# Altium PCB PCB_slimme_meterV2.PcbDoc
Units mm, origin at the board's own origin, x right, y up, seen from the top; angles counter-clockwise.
Board outline 25.4 x 59.2 mm, 2 copper layers (Top Layer, Bottom Layer); 37 components, 30 nets, 143 pads, 37 vias.
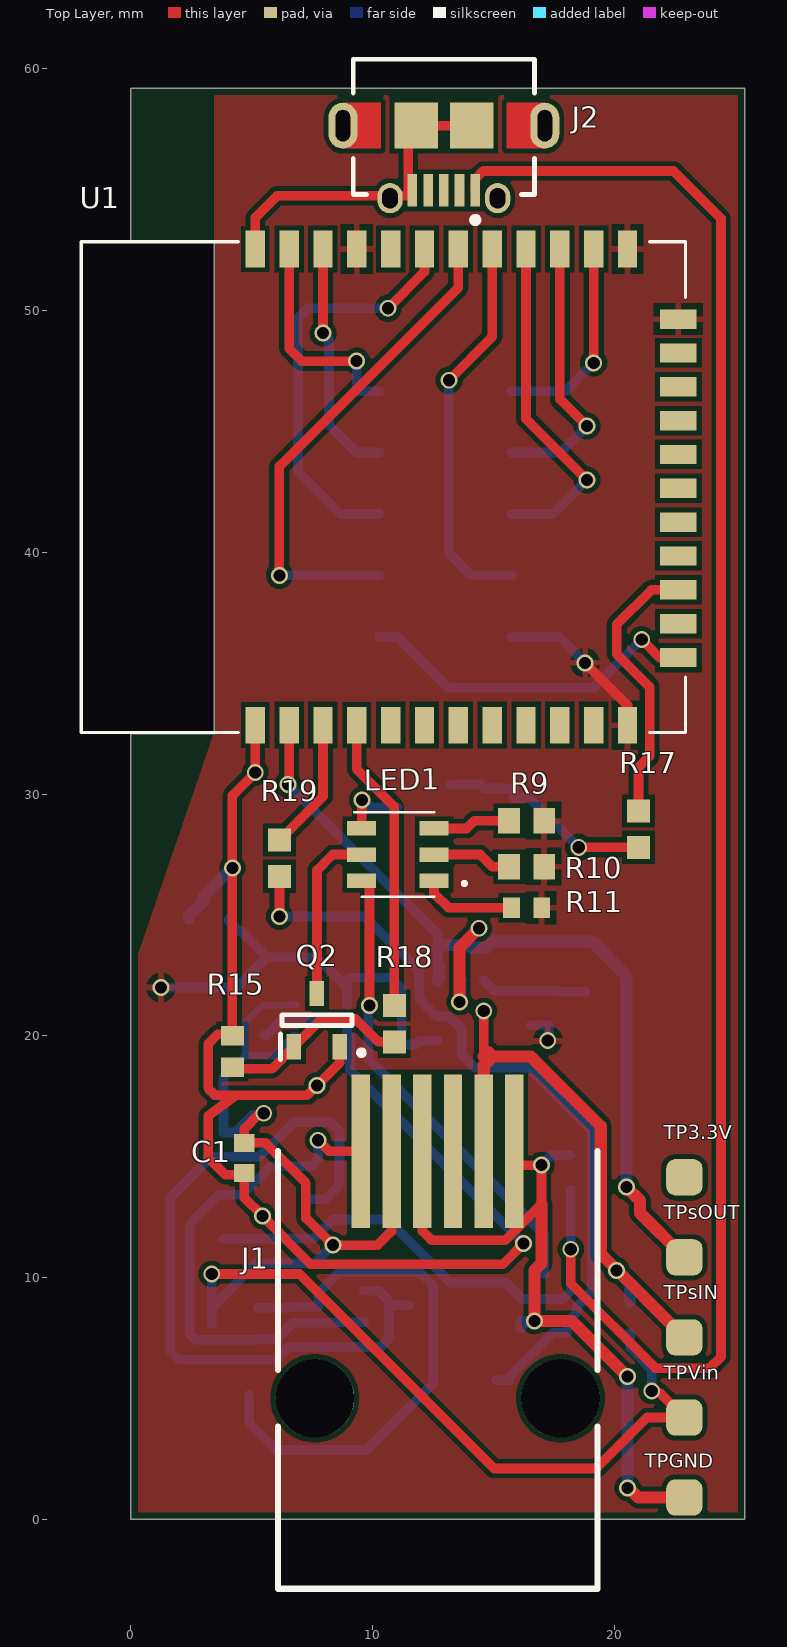
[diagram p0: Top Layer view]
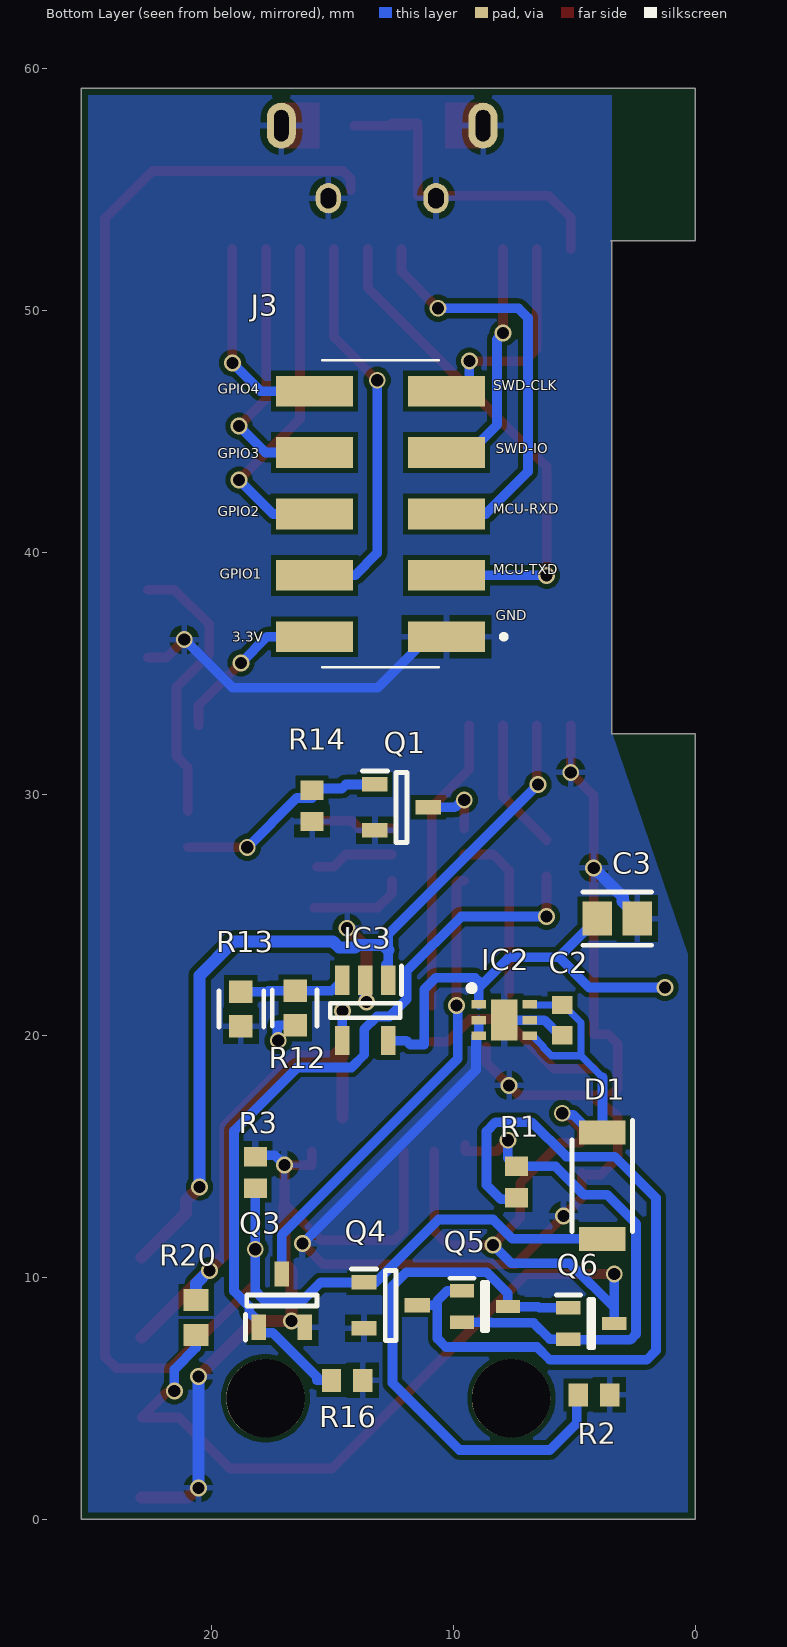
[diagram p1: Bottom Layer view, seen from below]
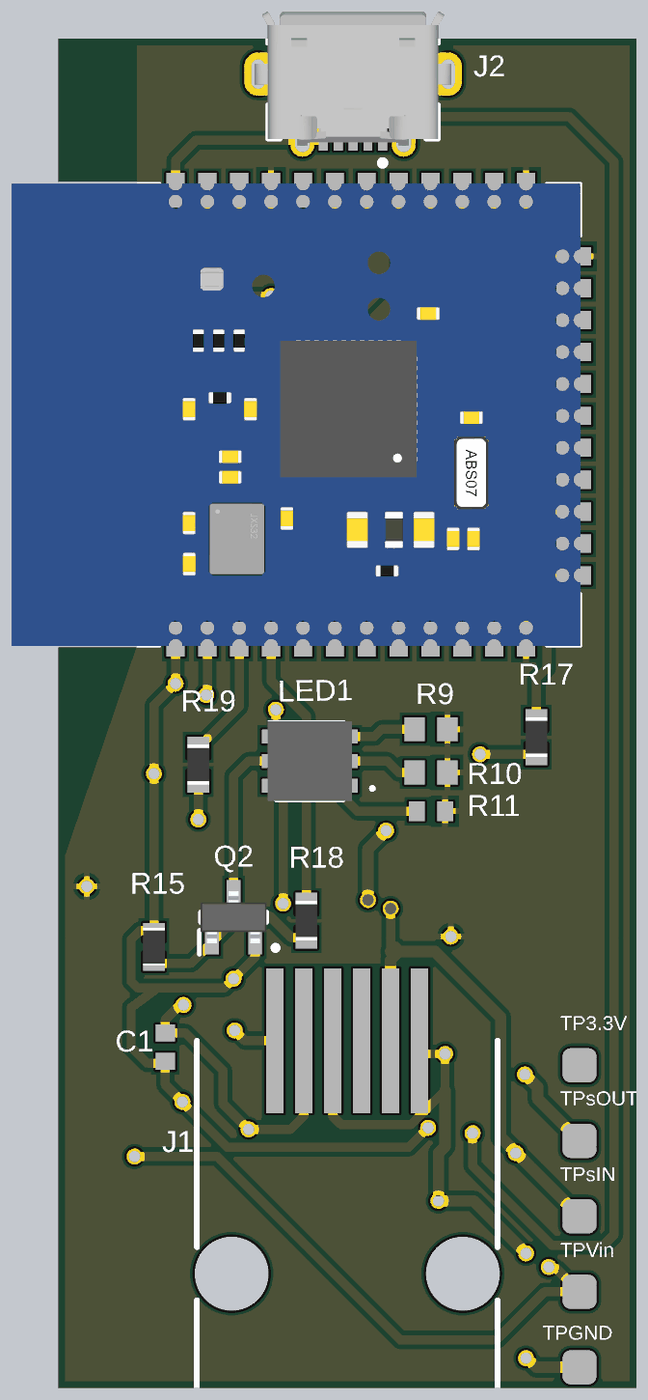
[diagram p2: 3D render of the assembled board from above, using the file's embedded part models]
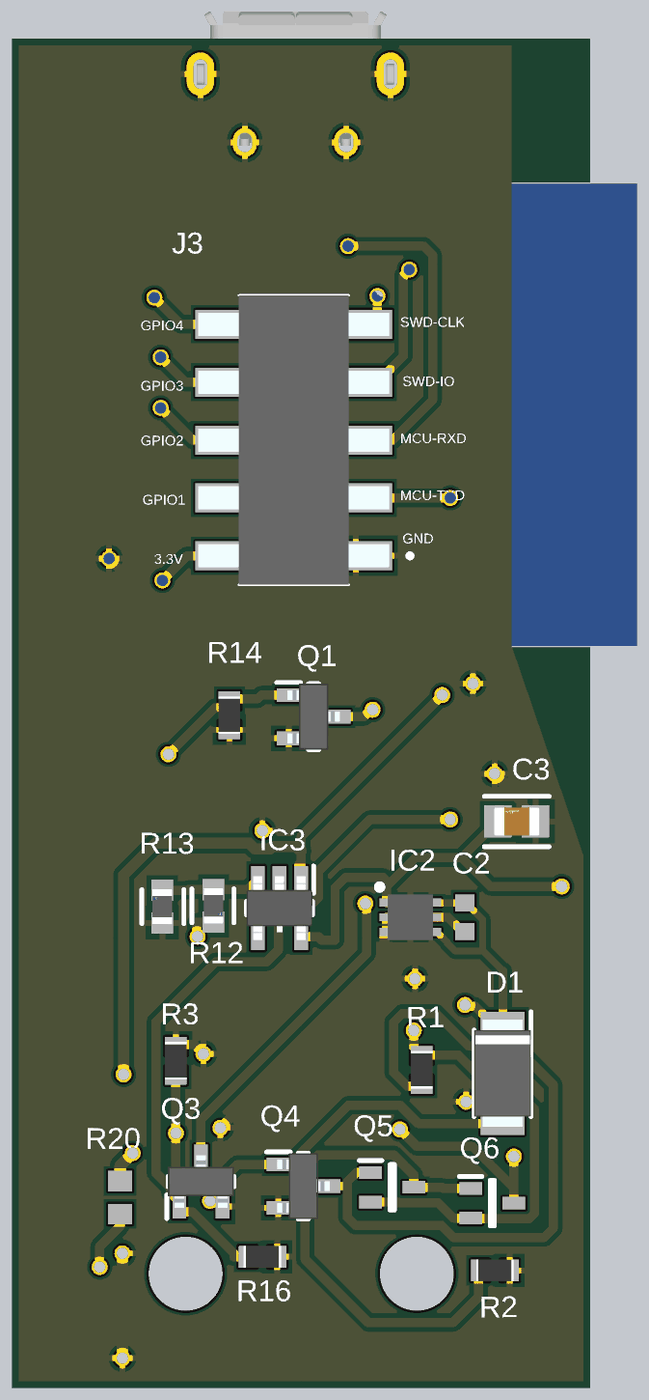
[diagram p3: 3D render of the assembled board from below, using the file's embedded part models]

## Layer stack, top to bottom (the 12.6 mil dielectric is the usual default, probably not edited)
Top Solder: solder mask 0.0102, Solder Resist, Dk 3.5
Top Layer: signal copper 0.0356
Dielectric 1: dielectric 0.32, FR-4, Dk 4.8
Bottom Layer: signal copper 0.0356
Bottom Solder: solder mask 0.0102, Solder Resist, Dk 3.5

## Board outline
3.5,52.9 3.45,52.85 3.45,32.5 0,32.5 0,0 25.4,0 25.4,59.2 0,59.2 0,52.9

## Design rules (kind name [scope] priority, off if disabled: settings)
AssemblyTestpoint [All] p1: testpointundercomponent=TRUE minsize=1 maxsize=2.5 preferedsize=1 minholesize=0 maxholesize=1 preferedholesize=0.8 testpointgrid=0.025 usegrid=TRUE gridtolerance=0 allowsidetop=TRUE allowsidebottom=TRUE
AssemblyTestpoint AssemblyTestpoint_1 [All] p2: testpointundercomponent=TRUE minsize=1.016 maxsize=2.54 preferedsize=1.524 minholesize=0 maxholesize=1.016 preferedholesize=0.813 testpointgrid=0.025 usegrid=TRUE gridtolerance=0 allowsidetop=TRUE allowsidebottom=TRUE
Clearance [All] p1: gap=0.2 ignorepadtopadclearanceinfootprint=FALSE except(0: Arc-Hole Track-Hole SMDPad-Hole THPad-Hole Via-Hole Fill-Hole Poly-Hole Region-Hole Text-Hole)
Clearance Clearance_2 [All] p2: gap=0.254 ignorepadtopadclearanceinfootprint=FALSE except(0: Arc-Hole Track-Hole SMDPad-Hole THPad-Hole Via-Hole Fill-Hole Poly-Hole Region-Hole Text-Hole)
HoleSize HoleSize_1 [All] p1: absolutevalues=TRUE maxlimit=10 minlimit=0.3 maxpercent=80.000 minpercent=20.000
HoleSize [All] p2: absolutevalues=TRUE maxlimit=2.54 minlimit=0.3 maxpercent=80.000 minpercent=20.000
MinimumSolderMaskSliver MinimumSolderMaskSliver_1 [(InComponent('J2') AND InComponent('IC2') AND InComponent('IC3'))] p1: minsoldermaskwidth=0.04
MinimumSolderMaskSliver MinimumSolderMaskSliver_2 [All] p2: minsoldermaskwidth=0.04
MinimumSolderMaskSliver [All] p3: minsoldermaskwidth=0.09
PolygonConnect [All] p1: connectstyle=Relief reliefconductorwidth=0.254 reliefentries=4 polygonreliefangle="90 Angle" airgapwidth=0.254
RoutingVias [All] p1: holewidth=0.5 width=0.7 viastyle="Through Hole" minholewidth=0.3 minwidth=0.4 maxholewidth=1 maxwidth=1.2
RoutingVias RoutingVias_1 [All] p2: holewidth=0.711 width=1.27 viastyle="Through Hole" minholewidth=0.711 minwidth=1.27 maxholewidth=0.711 maxwidth=1.27
SilkToSolderMaskClearance [HasFootprint('SON65P200X200X80-7N') AND (HasFootprint('SODFL4725X110N') AND HasFootprint('SOT65P210X110-3N') AND HasFootprint('SOT95P230X110-3N') AND HasFootprint('MOLX-47589-0001_V'))] p1: minsilkscreentomaskgap=0 clearancetoexposedcopper=TRUE
SilkToSolderMaskClearance SilkToSolderMaskClearance_1 [(InComponent('IC2') AND InComponent('IC3') AND InComponent('LED1') AND InComponent('J1') AND InComponent('J2'))] p2: minsilkscreentomaskgap=0.254 clearancetoexposedcopper=TRUE
SilkToSolderMaskClearance SilkToSolderMaskClearance_2 [IsPad] p3: minsilkscreentomaskgap=0.04 clearancetoexposedcopper=TRUE
SolderMaskExpansion [All] p1: expansion=0.102 istentingtop=FALSE
Width [All] p1: maxlimit=0.7 minlimit=0.3 preferedwidth=0.4
Width Width_1 [All] p2: maxlimit=0.254 minlimit=0.254 preferedwidth=0.254
26 further rules are at their usual default settings.

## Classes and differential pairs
component class Spanningsbronschakelaar: C1 D1 Q4 Q5 Q6 R1 R2 R3
component class schema_slimme_meterV4: C2 C3 IC2 IC3 J1 J2 J3 LED1 Q1 Q2 Q3 R9 R10 R11 R12 R13 R14 R15 R16 R17 R18 R19 R20 TP3.3V TPGND TPsIN TPsOUT TPVin U1

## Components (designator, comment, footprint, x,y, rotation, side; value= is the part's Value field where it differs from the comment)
C1 "1uF, 25V, 0603" CAPC1608X90X35LL10T15 4.7,14.95 r90 top
C2 "1uF, 25V, 0603" CAPC1608X90X35LL10T15 5.5,20.65 r90 bottom
C3 "4.7uF, 35V, 0805" FP-GRM219-0_15-0_1-IPC_B 3.226,24.85 r0 bottom
D1 "PMEG3020EP,115" SODFL4725X110N 3.85,13.8 r270 bottom
IC2 "TPS7A2533DRVR" SON65P200X200X80-7N 7.9,20.65 r180 bottom
IC3 "TLV9101IDBVR" SOT95P280X145-5N 13.65,21.05 r270 bottom
J1 "95501-6669" 95501-6669 12.695,5.007 r0 top
J2 "47589-0001" MOLX-47589-0001_V 12.95,56.15 r180 top
J3 "2x5_2.54mm_smd" 10129383910001ALF 13.02,41.59 r90 bottom
LED1 "L1MC-RGB0035000MP0" L1MCRGB0035000MP0 11.05,27.5 r180 top
Q1 "NX3020NAK,215" SOT95P230X110-3N 12.15,29.45 r180 bottom
Q2 "NX3020NAK,215" SOT95P230X110-3N 7.7,20.65 r90 top
Q3 "NX3020NAK,215" SOT95P230X110-3N 17.1,9.05 r90 bottom
Q4 "NX3020NAK,215" SOT95P230X110-3N 12.6,8.85 r180 bottom
Q5 "NX3008PBKW,115" SOT65P210X110-3N 8.7,8.8 r180 bottom
Q6 "NX3008PBKW,115" SOT65P210X110-3N 4.3,8.1 r180 bottom
R1 "10KΩ, 1/10W, 0603" RESC1609X50X30NL8T20 7.4,13.95 r90 bottom
R2 "10KΩ, 1/10W, 0603" RESC1609X50X30NL8T20 4.185,5.15 r0 bottom
R3 "10KΩ, 1/10W, 0603" RESC1609X50X30NL8T20 18.2,14.35 r270 bottom
R9 "18Ω, 0.1W, 0603" RESC1608X55X30ML15T15 16.375,28.9 r0 top
R10 "33Ω, 0.1W, 0603" RESC1608X55X30ML15T15 16.375,27 r0 top
R11 "82Ω, 0.1W, 0603" RESC1608X55X30LL15T15 16.375,25.3 r0 top
R12 "1MΩ, 1/10W, 0603" FP-CRCW0603-e3-IPC_B 16.55,21.15 r270 bottom
R13 "1MΩ, 1/10W, 0603" FP-CRCW0603-e3-IPC_B 18.8,21.115 r90 bottom
R14 "10KΩ, 1/10W, 0603" RESC1609X50X30NL8T20 15.85,29.515 r90 bottom
R15 "10KΩ, 1/10W, 0603" RESC1609X50X30NL8T20 4.2,19.35 r270 top
R16 "10KΩ, 1/10W, 0603" RESC1609X50X30NL8T20 14.4,5.75 r0 bottom
R17 "4.7KΩ, 1/10W, 0603" RESC1608X55X30NL15T15 21,28.55 r270 top
R18 "4.7KΩ, 1/10W, 0603" RESC1608X55X30NL15T15 10.9,20.5 r270 top
R19 "4.7KΩ, 1/10W, 0603" RESC1608X55X30NL15T15 6.15,27.35 r270 top
R20 "1.5KΩ, 1/10W, 0603" RESC1608X55X30ML15T15 20.65,8.35 r270 bottom
TP3.3V "TP_1" PCBComponent_1 22.9,14.15 r90 top
TPGND "TP_1" PCBComponent_1 22.9,0.9 r90 top
TPsIN "TP_1" PCBComponent_1 22.9,7.525 r90 top
TPsOUT "TP_1" PCBComponent_1 22.9,10.837 r90 top
TPVin "TP_1" PCBComponent_1 22.9,4.213 r90 top
U1 "ACN52832" ACN52832 22.95,32.55 r90 top

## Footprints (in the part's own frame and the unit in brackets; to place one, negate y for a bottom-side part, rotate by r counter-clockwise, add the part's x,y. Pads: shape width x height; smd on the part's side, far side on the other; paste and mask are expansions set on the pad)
95501-6669 [mm]
  rect 0.76x6.35 smd: 1(-3.175,10.225) 2(-1.905,10.225) 3(-0.635,10.225) 4(0.635,10.225) 5(1.905,10.225) 6(3.175,10.225)
  round 3.25 hole 3.25 unplated: 7(-5.08,0) 8(5.08,0)
  silkscreen extent -6.61,-7.88 6.61,14.39, body extent -6.61,-8 6.61,12.55, height 11.75
10129383910001ALF [mm]
  rect 1.27x3.18 smd: A1(-5.08,-2.73) A2(-2.54,-2.73) A3(0,-2.73) A4(2.54,-2.73) A5(5.08,-2.73) B1(-5.08,2.73) B2(-2.54,2.73) B3(0,2.73) B4(2.54,2.73) B5(5.08,2.73)
  silkscreen extent -6.35,-5.2 6.35,2.42, body extent -6.35,-4.19 6.35,4.19, height 9.95
ACN52832 [mm]
  rect 1.524x0.8 smd: 1(0.3,17.8) 2(0.3,16.4) 3(0.3,15) 4(0.3,13.6) 5(0.3,12.2) 6(0.3,10.8) 7(0.3,9.4) 8(0.3,8) 9(0.3,6.6) 10(0.3,5.2) 11(0.3,3.8) 12(0.3,2.4) 24(20,2.4) 25(20,3.8) 26(20,5.2) 27(20,6.6) 28(20,8) 29(20,9.4) 30(20,10.8) 31(20,12.2) 32(20,13.6) 33(20,15) 34(20,16.4) 35(20,17.8)
  rect 0.8x1.524 smd: 13(3.1,0.3) 14(4.5,0.3) 15(5.9,0.3) 16(7.3,0.3) 17(8.7,0.3) 18(10.1,0.3) 19(11.5,0.3) 20(12.9,0.3) 21(14.3,0.3) 22(15.7,0.3) 23(17.1,0.3)
  Top Layer pour cut-out: 20.3,25 20.3,19.5 0,19.5 0,25
  Bottom Layer pour cut-out: 20.3,25 20.3,19.5 0,19.5 0,25
  silkscreen extent 0,0 20.3,25, body extent 0,0 20.3,25, height 1.8
CAPC1608X90X35LL10T15 [mm] "Chip Capacitor, 2-Leads, Body 1.60x0.80mm, IPC High Density"
  rect 0.75x0.85 smd: 1(-0.625,0) 2(0.625,0)
  body extent -0.85,-0.45 0.85,0.45, height 0.9
FP-CRCW0603-e3-IPC_B [mm]
  rect 0.935x0.962 smd paste+0 mask+0: 1(-0.715,0) 2(0.715,0)
  silkscreen extent -0.75,-0.95 0.75,0.9, body extent -0.77,-0.43 0.77,0.43, height 0.5
FP-GRM219-0_15-0_1-IPC_B [mm]
  rect 1.206x1.408 smd paste+0 mask+0: 1(-0.826,0) 2(0.826,0)
  silkscreen extent -1.43,-1.1 1.43,1.1, body extent -1,-0.63 1,0.63, height 0.95
L1MCRGB0035000MP0 [mm]
  rect 1.2x0.6 smd: 1(-1.5,1.08) 2(1.5,1.08) 3(-1.5,0) 4(1.5,0) 5(-1.5,-1.08) 6(1.5,-1.08)
  silkscreen extent -2.8,-1.75 1.8,1.75, body extent -1.85,-1.75 1.85,1.75, height 2.9
MOLX-47589-0001_V [mm] "SMD, 5-Leads, Body 7.5x5.6mm, Pitch 0.65mm"
  rect 0.4x1.35 smd: 1(-1.3,1.175) 2(-0.65,1.175) 3(0,1.175) 4(0.65,1.175) 5(1.3,1.175)
  oval 1.05x1.25 hole 0.65 slot 0.85 at 90 deg: 6(-2.225,1.5) 7(2.225,1.5)
  oval 1.2x1.9 hole 0.6 slot 1.3 at 90 deg: 8(-4.175,-1.5) 11(4.175,-1.5)
  rect 1.8x1.9 smd: 9(-1.15,-1.5) 10(1.15,-1.5)
  Top Layer region: 2.6,-2.45 4.175,-2.45 4.175,-0.55 2.6,-0.55
  Top Layer region: -2.6,-0.55 -4.175,-0.55 -4.175,-2.45 -2.6,-2.45
  silkscreen extent -3.75,-4.25 3.75,2.52, body extent -4.32,-4.25 4.32,1.64, height 2.74
PCBComponent_1 [mm]
  rrect50% 1.5x1.5 smd: TP1(0,0)
RESC1608X55X30LL15T15 [mm] "Chip Resistor, 2-Leads, Body 1.60x0.80mm, IPC High Density"
  rect 0.7x0.85 smd: 1(-0.625,0) 2(0.625,0)
  body extent -0.87,-0.48 0.87,0.48, height 0.55
RESC1608X55X30ML15T15 [mm] "Chip Resistor, 2-Leads, Body 1.60x0.80mm, IPC Low Density"
  rect 0.9x1.05 smd: 1(-0.725,0) 2(0.725,0)
  body extent -0.87,-0.48 0.87,0.48, height 0.55
RESC1608X55X30NL15T15 [mm] "Chip Resistor, 2-Leads, Body 1.75x0.95mm, IPC Medium Density"
  rect 0.95x0.95 smd: 1(-0.75,0) 2(0.75,0)
  body extent -0.87,-0.48 0.87,0.48, height 0.55
RESC1609X50X30NL8T20 [mm] "Chip Resistor, 2-Leads, Body 1.65x0.95mm, IPC Medium Density"
  rect 0.8x0.95 smd: 1(-0.65,0) 2(0.65,0)
  body extent -0.82,-0.48 0.82,0.48, height 0.5
SODFL4725X110N [mm]
  rect 1x1.93 smd: 1(-2.2,0) 2(2.2,0)
  silkscreen extent -2.7,-1.25 1.9,1.25, body extent -2.35,-1.25 2.35,1.25, height 1.1
SON65P200X200X80-7N [mm]
  rect 0.6x0.35 smd: 1(-1.05,0.65) 2(-1.05,0) 3(-1.05,-0.65) 4(1.05,-0.65) 5(1.05,0) 6(1.05,0.65)
  rect 1.1x1.7 smd: 7(0,0)
  silkscreen extent -1.48,1.2 -1.23,1.45, body extent -1,-1 1,1, height 0.8
SOT65P210X110-3N [mm]
  rect 1x0.55 smd: 1(-0.95,0.65) 2(-0.95,-0.65) 3(0.95,0)
  silkscreen extent -1.45,-1 0.1,1.17, body extent -1.05,-1.05 1.05,1.05, height 0.95
SOT95P230X110-3N [mm]
  rect 1.05x0.6 smd: 1(-1.1,0.95) 2(-1.1,-0.95) 3(1.1,0)
  silkscreen extent -1.63,-1.45 0.22,1.5, body extent -1.15,-1.45 1.15,1.45, height 1.1
SOT95P280X145-5N [mm]
  rect 1.2x0.6 smd: 1(-1.25,0.95) 2(-1.25,0) 3(-1.25,-0.95) 4(1.25,-0.95) 5(1.25,0.95)
  silkscreen extent -1.85,-1.45 0.3,1.5, body extent -1.4,-1.45 1.4,1.45, height 1.2

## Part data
C1 C2: library part CMP-2006-02459-1, Manufacturer=Murata, Part Number=GRM188R61E105KA12D
C3: library part CMP-06035-049019-1, "Chip Multilayer Ceramic Capacitors for General Purpose, 0805, 4.7uF, X5R, 15%, 10%, 35V", Capacitance=4.7uF, Case Code (Imperial)=0805, Case Code (Metric)=2012, Dielectric=X5R, Dielectric Material=Ceramic, Max Operating Temperature=85°C, Min Operating Temperature=-55°C, Package Quantity=1, Tolerance=10%, Voltage=35V
D1: "Diode", Manufacturer_Name=Nexperia, Mouser2 Part Number=771-PMEG3020EP115
IC2 IC3: "Integrated Circuit", Manufacturer_Name="Texas Instruments"
J1: "Connector", Manufacturer_Name=Molex, Mouser2 Part Number=538-95501-6669
J2: library part CMP-2000-05610-1, "Right Angle Female Type AB Micro USB Connector, 30 V, 1.8 A, -30 to 85 degC, RoHS, Tape and Reel", Color=Black, Current Rating=1.8A, Manufacturer=Molex, Operating Temperature Range=-20Cto+85C, Package Description="Micro USB Connector, Pitch 0.65 mm, 5 Positions, Body 7.5 x 5.6 mm", Voltage Rating=30VAC
J3: "Connector", Manufacturer_Name=Amphenol, Manufacturer_Part_Number=10129383-910001ALF
LED1: "LED", Manufacturer_Name=Lumileds
Q1 Q2 Q3 Q4: "MOSFET (N-Channel)", Manufacturer_Name=Nexperia
Q5 Q6: "MOSFET (P-Channel)", Manufacturer_Name=Nexperia
R1 R2 R3 R14 R15 R16: library part CMP-1666-00005-4, "Chip Resistor, 10 KOhm, +/- 1%, 100 mW, -55 to 155 degC, 0603 (1608 Metric), RoHS, Tape and Reel", Manufacturer="Vishay Semiconductor", Max Operating Temperature="155 degC", Min Operating Temperature="-55 degC", Package Quantity=5000, Voltage Rating="75 V"
R9: library part CMP-2000-00306-1, Manufacturer=Panasonic, Part Number=ERJ3EKF18R0V
R10: library part CMP-2000-00443-1, Manufacturer=Panasonic, Part Number=ERJ3EKF33R0V
R11: library part CMP-2000-00662-1, Manufacturer=Panasonic, Part Number=ERJ3EKF82R0V
R12 R13: library part CMP-2000-03016-2, "RES Thick Film, 1MΩ, 5%, 0.1W, 200ppm/°C, 0603", Case Code (Imperial)=0603, Case Code (Metric)=1608, Max Operating Temperature=155°C, Max Power Dissipation=100mW, Min Operating Temperature=-55°C, Package Quantity=1, Resistance=1MR, Temperature Coefficient=200ppm/°C, Tolerance=5%, Voltage Rating=75V
R17 R18 R19: library part CMP-1012-00586-3, "Precision Thick Film Chip Resistor, 4.7 KOhm, +/- 1%, -55 to 155 degC, 0603 (1608 Metric), RoHS, Tape and Reel", Case Code (Imperial)=1206, Case Code (Metric)=3216, Case\Package=1205, Max Operating Temperature="125 degC", Min Operating Temperature="-55 degC", Package Quantity=1, Power Rating="250 mW", Resistance="220 Ohm", Tolerance=5%, Type (Resistor)="Thick Film", Voltage Rating="50 V"
R20: library part CMP-1012-00528-2, Manufacturer=Panasonic, Part Number=ERJ-3EKF1501V
TP3.3V TPGND TPsIN TPsOUT TPVin: library part TestPoint
U1: "Bluetooth-Module (802.15.1) Bluetooth Low Energy Smart Module"

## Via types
v1: diameter 0.7, hole 0.5, Top Layer to Bottom Layer, 37 vias

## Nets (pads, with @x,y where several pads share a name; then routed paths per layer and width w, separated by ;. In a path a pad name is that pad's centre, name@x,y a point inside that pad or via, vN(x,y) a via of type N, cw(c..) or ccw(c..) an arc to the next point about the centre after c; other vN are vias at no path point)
3.3V: C3.2 IC2.1 IC3.5 J3.B1 R9.2 R10.2 R11.2 R12.2 U1.12 U1.23 U1.24 U1.32 | length 26.6
  Top Layer w0.4: v1(18.794,35.43) 20.55,33.675 U1.12
  Bottom Layer w0.4: v1(1.25,22) 4.387,22 5.645,23.258 ; C3.2 4.052,24.749 4.455,24.346 4.557,24.346 5.645,23.258 ; IC2.1 8.95,22 ; IC3.5 11.95,19.8 11.793,19.643 11.207,19.643 11.207,21.931 10.738,22.4 9.1,22.4 8.95,22.25 8.95,22 ; J3.B1 17.715,36.51 v1(18.794,35.43) ; R12.2 17.296,20.435 17.296,19.846 v1(17.25,19.8) ; 5.645,23.258 7.692,23.258 8.95,22
Blue_led: R17.1 U1.15 | length 11.6
  Top Layer w0.4: R17.1 21,31.108 21.461,31.569 21.461,34.44 20.102,35.799 20.102,37.018 21.535,38.45 U1.15
GND: C1.1 C2.1 C3.1 IC2.2 IC2.3 IC2.5 IC2.7 IC3.2 J1.3 J1.6 J2.5 J2.6 J2.7 J2.8 J2.9 J2.10 J2.11 J3.A1 Q1.2 Q2.2 Q3.2 Q4.2 R2.1 R3.1 R13.1 R14.1 R15.1 R16.1 TPGND.TP1 U1.1 U1.13 U1.35 | length 124.2
  Top Layer w0.4: C1.1@4.7,14.25 3.91,14.25 3.199,14.961 3.199,16.685 4.367,17.549 ; C1.1 4.7,13.3 5.439,12.561 5.439,12.539 7.427,10.552 15.392,10.552 v1(16.248,11.408) ; U1.1 v1(5.15,30.9) 4.2,29.95 v1(4.2,26.95) 4.2,20.065 3.592,20.065 3.199,19.672 3.199,17.828 3.478,17.549 4.367,17.549 ; U1.35 5.15,53.85 6.05,54.75 10.725,54.75 11.475,54.75 11.475,57.75 J2.10@12.55,57.75 ; Q2.2 8.65,18.895 7.304,17.549 4.367,17.549 ; J2.10 J2.9 ; J1.3 12.06,11.923 12.433,11.55 15.497,11.55 16.127,12.18 16.991,13.044 v1(16.991,14.653) 15.87,14.653 J1.6 ; v1(21.137,36.389) 21.877,35.65 U1.13
  Top Layer w0.5: v1(13.607,21.407) 13.607,23.657 v1(14.4,24.45) ; 16.991,13.044 16.991,10.591 16.7,10.3 v1(16.7,8.2) 18.25,8.2 v1(20.55,5.9) ; v1(20.55,1.3) 20.599,1.3 20.999,0.9 TPGND.TP1
  Bottom Layer w0.4: C2.1 5.616,20.025 6.241,20.65 IC2.5 IC2.7 ; IC2.2 IC2.3 9.066,20 9.066,18.59 v1(16.248,11.408) ; J3.A1 11.022,36.51 13.13,34.402 19.15,34.402 v1(21.137,36.389) ; v1(16.991,14.653) 17.403,15.065 R3.1@18.2,15.065
  Bottom Layer w0.5: C3.1 2.4,24.951 3,25.551 3,25.75 v1(4.2,26.95) ; v1(13.607,21.407) 13.628,21.428 13.628,22.278 IC3.2 ; Q3.2 16.15,8.112 16.2,8.162 16.662,8.162 v1(16.7,8.2) ; v1(20.55,1.3) v1(20.55,5.9)
  other v1: 5.45,12.55 7.7,17.95
GPIO1: J3.B2 U1.28 | length 16.3
  Top Layer w0.4: v1(13.156,47.12) 14.95,48.915 U1.28
  Bottom Layer w0.4: v1(13.156,47.12) 13.156,39.964 14.07,39.05 J3.B2
GPIO2: J3.B3 U1.27 | length 14.3
  Top Layer w0.4: U1.27 16.35,45.52 v1(18.871,42.999)
  Bottom Layer w0.4: J3.B3 17.461,41.59 v1(18.871,42.999)
GPIO3: J3.B4 U1.26 | length 11.4
  Top Layer w0.4: U1.26 17.75,46.343 v1(18.871,45.222)
  Bottom Layer w0.4: J3.B4 17.778,44.13 v1(18.871,45.222)
GPIO4: J3.B5 U1.25 | length 8.6
  Top Layer w0.4: v1(19.15,47.838) U1.25
  Bottom Layer w0.4: J3.B5 17.982,46.67 v1(19.15,47.838)
Green_led: R18.1 U1.4 | length 12.2
  Top Layer w0.4: U1.4 9.35,31.024 10.9,29.474 R18.1
MCU-RXD: J3.A3 U1.30 | length 17.4
  Top Layer w0.4: v1(10.638,50.098) 12.15,51.61 U1.30
  Bottom Layer w0.4: J3.A3 8.672,41.59 6.921,43.341 6.921,49.705 7.314,50.098 v1(10.638,50.098)
MCU-TXD: J3.A2 U1.29 | length 20.7
  Top Layer w0.4: v1(6.145,39.05) 6.145,43.551 13.55,50.956 U1.29
  Bottom Layer w0.4: v1(6.145,39.05) J3.A2
NetD1_2: D1.2 J2.1 Q4.1 R3.2 | length 88.3
  Top Layer w0.4: J2.1 14.25,55.45 14.576,55.776 22.452,55.776 24.415,53.813 24.415,6.719 23.946,6.25 21.698,6.25 18.2,9.748 v1(18.2,11.173)
  Bottom Layer w0.4: D1.2 7.558,11.6 8.362,12.404 10.621,12.404 13.225,9.8 Q4.1 15.492,9.8 16.177,9.116 17.88,9.116 18.2,9.436 v1(18.2,11.173) R3.2@18.2,13.635
NetIC3_3: IC3.3 R12.1 R13.2 | length 4.4
  Bottom Layer w0.4: IC3.3 15.035,21.865 R12.1 17.651,21.865 17.686,21.831 R13.2
NetJ1_1: J1.1 Q5.2 Q6.2 R1.2 | length 21.6
  Top Layer w0.4: v1(7.75,15.681) 8.199,15.232 J1.1 J1.1@9.52,15.501
  Bottom Layer w0.4: v1(7.75,15.681) 7.75,14.95 7.675,14.875 7.675,14.8 7.475,14.6 R1.2 5.781,14.6 4.614,13.433 3.652,13.433 2.45,12.231 2.45,7.659 2.684,7.425 5.225,7.425 Q6.2 6.018,7.45 6.693,8.125 8.416,8.125 8.441,8.15 Q5.2
NetLED1_1: LED1.1 R11.1 | length 4
  Top Layer w0.4: LED1.1 12.546,26.42 12.546,25.893 13.139,25.3 R11.1
NetLED1_2: LED1.2 Q3.3 | length 19.6
  Top Layer w0.4: LED1.2 9.775,26.42 9.875,26.32 v1(9.875,21.25)
  Bottom Layer w0.4: v1(9.875,21.25) 9.818,21.193 9.818,19.058 17.1,11.775 Q3.3
NetLED1_3: LED1.3 R10.1 | length 3.3
  Top Layer w0.4: LED1.3 14.45,27.5 14.95,27 R10.1
NetLED1_4: LED1.4 Q2.3 | length 7.2
  Top Layer w0.4: Q2.3 7.7,26.845 8.355,27.5 LED1.4
NetLED1_5: LED1.5 R9.1 | length 3.2
  Top Layer w0.4: LED1.5 13.892,28.58 14.212,28.9 R9.1
NetLED1_6: LED1.6 Q1.3 | length 2.8
  Top Layer w0.4: LED1.6 9.557,28.587 v1(9.557,29.757)
  Bottom Layer w0.4: v1(9.557,29.757) 9.638,29.757 9.945,29.45 Q1.3
NetQ1_1: Q1.1 R14.2 R17.2 | length 9.1
  Top Layer w0.4: v1(18.531,27.8) R17.2
  Bottom Layer w0.4: Q1.1 14.451,30.4 14.62,30.231 15.85,30.231 15.85,29.842 16.489,29.842 v1(18.531,27.8)
NetQ2_1: Q2.1 R15.2 R18.2 | length 7.9
  Top Layer w0.4: R15.2@4.2,18.635 5.835,18.635 Q2.1 7.898,20.698 9.295,20.698 10.243,19.75 R18.2
NetQ3_1: Q3.1 R16.2 R19.2 | length 32.2
  Top Layer w0.4: v1(6.15,24.94) R19.2
  Bottom Layer w0.4: v1(6.15,24.94) 9.676,24.94 11.936,22.679 11.936,21.514 12.65,20.8 13.166,20.8 13.692,20.274 13.692,19.218 14.219,18.692 16.458,18.692 19.081,16.068 19.081,9.436 18.45,8.805 18.45,8.575 18.05,8.175 18.05,7.719 17.482,7.719 15.65,5.887 15.65,5.75 R16.2@15.115,5.75
NetQ4_3: Q4.3 Q5.1 R1.1 | length 31.6
  Bottom Layer w0.4: R1.1@7.4,13.235 8.042,13.235 8.634,13.828 8.634,16.05 8.253,16.431 6.763,16.431 5.332,15 3.33,15 1.624,13.294 1.624,6.982 2.005,6.601 6.018,6.601 6.549,7.132 10.321,7.132 10.666,7.478 10.666,8.85 ; Q5.1 10.26,9.45 10.666,9.044 10.666,8.85 ; Q4.3 10.666,8.85
NetQ5_3: Q5.3 Q6.1 R2.2 | length 22.9
  Bottom Layer w0.4: R2.2@4.9,5.15 4.9,3.985 6.017,2.867 9.752,2.867 12.525,5.64 12.525,9.65 11.95,10.225 8.634,10.225 7.75,9.341 Q5.3 6.5,8.8 6.45,8.75 Q6.1
Red_led: R19.1 U1.3 | length 5.5
  Top Layer w0.4: R19.1 7.95,29.9 U1.3
Signal_out: IC3.1 TPsOUT.TP1 U1.2 | length 34.4
  Top Layer w0.4: v1(6.5,30.4) 6.55,30.45 U1.2
  Top Layer w0.5: v1(20.5,13.75) 21.063,13.187 21.063,12.675 TPsOUT.TP1
  Bottom Layer w0.4: v1(6.5,30.4) 12.7,24.2 12.7,23.65 12.7,22.936
  Bottom Layer w0.5: IC3.1 12.75,22.35 12.75,22.936 ; 12.7,23.55 12.9,23.75 13.969,23.75 14.069,23.65 14.731,23.65 14.981,23.9 19.1,23.9 20.5,22.5 v1(20.5,13.75)
sIN: IC3.4 J1.5 R20.1 TPsIN.TP1 | length 23.7
  Top Layer w0.4: 14.6,19.149 v1(14.6,21.028)
  Top Layer w0.5: J1.5@14.6,16.63 14.6,18.771 14.978,19.149 ; 14.6,19.149 14.789,19.339 14.978,19.149 ; TPsIN.TP1 19.44,10.985 19.44,16.26 16.551,19.149 14.978,19.149
  Bottom Layer w0.4: IC3.4 v1(14.6,21.028)
  Bottom Layer w0.5: v1(20.1,10.3) 20.65,9.75 R20.1@20.65,9
SWD-CLK: J3.A5 U1.34 | length 9.3
  Top Layer w0.4: U1.34 6.55,48.435 7.072,47.913 v1(9.346,47.913)
  Bottom Layer w0.4: v1(9.346,47.913) 9.346,46.67 J3.A5
SWD-IO: J3.A4 U1.33 | length 9.9
  Top Layer w0.4: v1(7.95,49.069) U1.33
  Bottom Layer w0.4: v1(7.95,49.069) 8.2,48.819 8.2,45.276 9.346,44.13 J3.A4
Vin: C1.2 C2.2 D1.1 IC2.4 IC2.6 J1.2 Q6.3 R20.2 TPVin.TP1 | length 62.8
  Top Layer w0.4: v1(3.35,10.15) 6.98,10.15 15.03,2.1 19.25,2.1 21.363,4.213 TPVin.TP1 21.87,5.243 21.607,5.243 v1(21.55,5.3) ; v1(5.5,16.799) 5.443,16.741 5.291,16.741 4.7,16.15 4.7,15.65 4.775,15.575 5.573,15.575 7.239,13.909 7.239,12.461 v1(8.359,11.341) 10.208,11.341 10.79,11.923 J1.2
  Bottom Layer w0.3: 3.834,18.282 4.725,19.173 ; IC2.4 6.725,20 6.275,19.55 6.275,19.505 5.943,19.173 4.725,19.173 ; IC2.6 6.725,21.3 6.7,21.275 C2.2 5.45,21.275 4.725,20.55 4.725,19.173
  Bottom Layer w0.4: v1(3.35,10.15) 3.35,8.759 ; 3.834,18.282 3.834,16 4.315,16 5.056,16.741 5.443,16.741 v1(5.5,16.799) ; v1(8.359,11.341) 7.607,10.589 5.18,10.589 3.35,8.759 ; R20.2@20.65,7.7 20.65,7.1 21.55,6.2 v1(21.55,5.3) ; 3.35,8.759 Q6.3 3.35,8.759
pads on no net: J1.4 J1.7 J1.8 J2.2 J2.3 J2.4 TP3.3V.TP1 U1.5 U1.6 U1.7 U1.8 U1.9 U1.10 U1.11 U1.14 U1.16 U1.17 U1.18 U1.19 U1.20 U1.21 U1.22 U1.31

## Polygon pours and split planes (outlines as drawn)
GND on Bottom Layer "GND_L02_P002" (solid, pour order 2): 3.45,58.9 25.1,58.9 25.1,0.3 0.3,0.3 0.3,23.374 3.45,32.55 3.45,52.85
3.3V on Top Layer "3.3V_L01_P000" (solid, pour order 0): 3.45,58.9 25.1,58.9 25.1,0.3 0.3,0.3 0.3,23.374 3.45,32.55 3.45,52.85

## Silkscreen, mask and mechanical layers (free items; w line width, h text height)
Bottom Overlay:
  text "SWD-CLK" at 8.35,46.558 h0.7
  text "GPIO4" at 19.753,46.408 h0.7
  text "SWD-IO" at 8.25,43.958 h0.7
  text "GPIO3" at 19.754,43.758 h0.7
  text "MCU-RXD" at 8.35,41.458 h0.7
  text "GPIO2" at 19.75,41.358 h0.7
  text "MCU-TXD" at 8.35,38.958 h0.7
  text "GPIO1" at 19.668,38.758 h0.7
  text "GND" at 8.25,37.058 h0.7
  text "3.3V" at 19.158,36.158 h0.7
